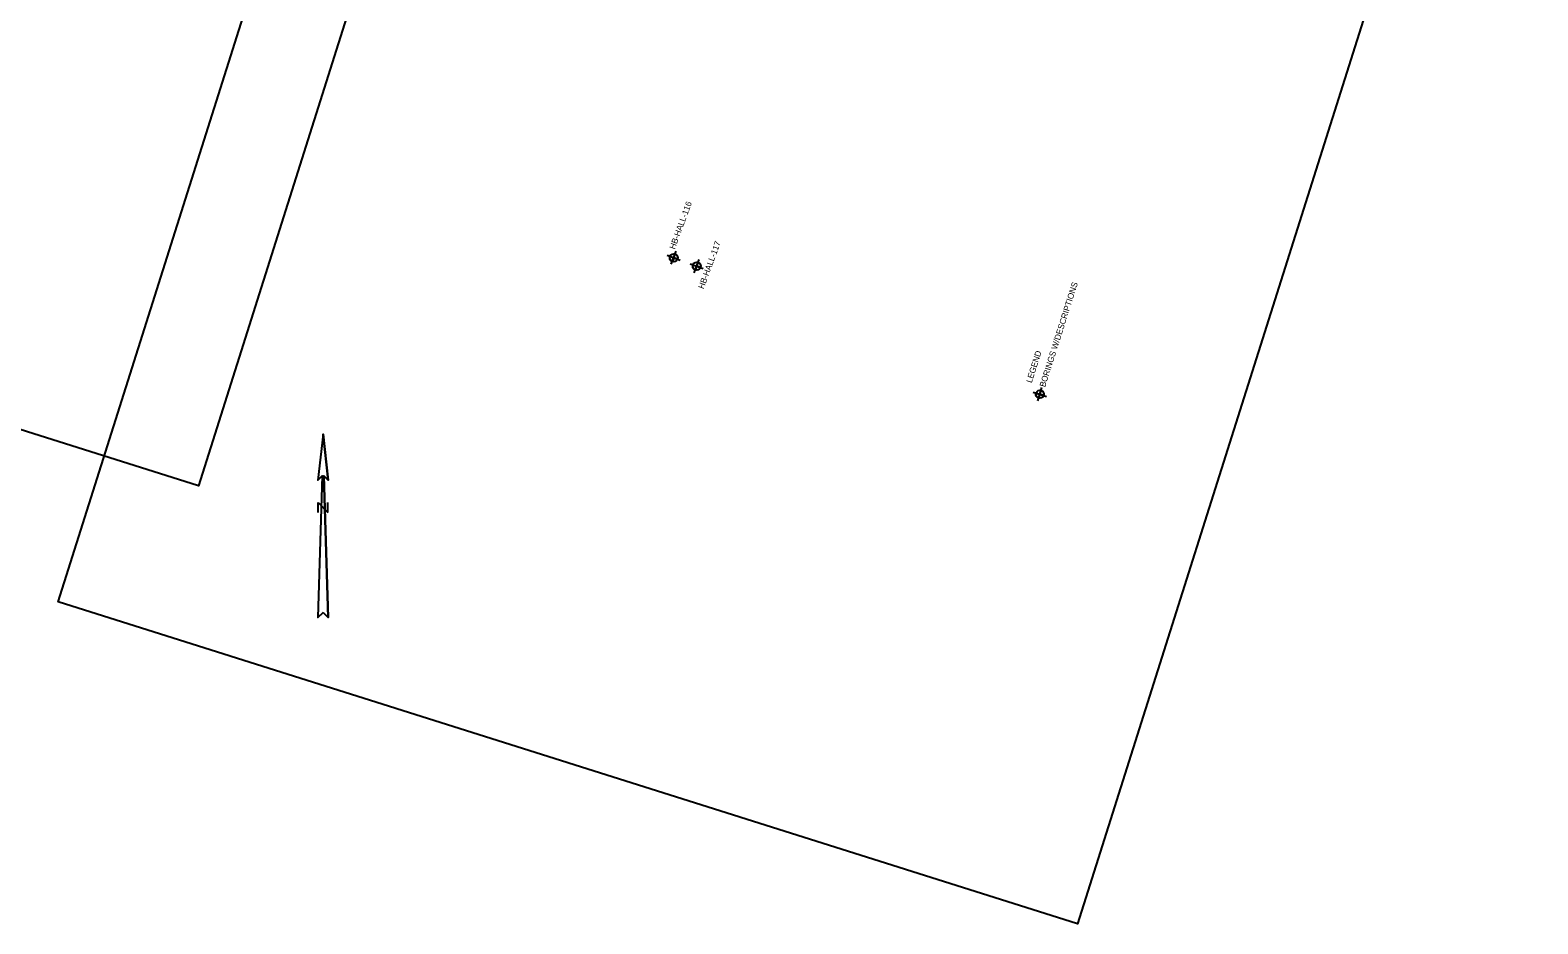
# Model space of a CAD drawing. Extents: x 1136334 to 1137758, y 528745 to 531454.
# Drawn here: x 1136833 to 1137574, y 528745 to 529184 of the extents above; entities that cross this region are included whole.
import ezdxf

# ---------------------------------------------------------------- set-up
doc = ezdxf.new("R2010")
doc.units = 0
for name, color, linetype in [('H_V CONTROLS', 7, 'Continuous'), ('PLOT BOUNDARY', 7, 'Continuous'), ('ROCKS', 7, 'Continuous')]:
    doc.layers.add(name, color=color, linetype=linetype)

msp = doc.modelspace()

# ---------------------------------------------------------------- linework, layer by layer
at = {"layer": 'H_V CONTROLS'}
for p, q in [((1137325.97, 529006.4), (1137332.54, 529004.33)), ((1137328.22, 529002.08), (1137330.29, 529008.65)), ((1136977.28, 528985.74), (1136974.78, 528963.24)), ((1136977.28, 528985.74), (1136979.78, 528963.24)), ((1136976.9, 528965.36), (1136974.78, 528963.24)), ((1136976.9, 528965.36), (1136974.78, 528895.74)), ((1136977.67, 528965.36), (1136979.78, 528963.24)), ((1136977.67, 528965.36), (1136979.78, 528895.74)), ((1136977.28, 528898.24), (1136974.78, 528895.74)), ((1136977.28, 528898.24), (1136979.78, 528895.74))]:
    msp.add_line(p, q, dxfattribs=at)
for points in [[(1137329.26, 529005.37), (1137328.66, 529003.49), (1137328.41, 529003.59), (1137328.17, 529003.73), (1137327.95, 529003.9), (1137327.73, 529004.12), (1137327.59, 529004.32), (1137327.42, 529004.65), (1137327.35, 529004.87), (1137327.29, 529005.32), (1137327.31, 529005.67), (1137327.38, 529005.96)], [(1137329.26, 529005.37), (1137329.85, 529007.24), (1137330.1, 529007.14), (1137330.34, 529007.01), (1137330.56, 529006.84), (1137330.78, 529006.61), (1137330.93, 529006.41), (1137331.09, 529006.09), (1137331.16, 529005.87), (1137331.22, 529005.41), (1137331.2, 529005.06), (1137331.13, 529004.78)]]:
    msp.add_lwpolyline(points, close=True, dxfattribs=at)
for points in [[(1136977.28, 528898.24), (1136979.78, 528895.74), (1136977.67, 528965.36), (1136979.78, 528963.24), (1136977.28, 528985.74), (1136974.78, 528963.24), (1136976.9, 528965.36), (1136974.78, 528895.74), (1136977.28, 528898.24)], [(1136974.92, 528947.24), (1136974.92, 528952.24)], [(1136974.92, 528952.24), (1136979.65, 528947.24)], [(1136979.65, 528947.24), (1136979.65, 528952.24)]]:
    msp.add_lwpolyline(points, dxfattribs=at)
msp.add_circle((1137329.26, 529005.37), 1.97, dxfattribs=at)
at = {"layer": 'PLOT BOUNDARY'}
for points in [[(1137142.07, 529675.56), (1136916.06, 528960.42), (1136415.46, 529118.63), (1136641.47, 529833.77)], [(1137573.8, 529460.37), (1137347.79, 528745.23), (1136847.2, 528903.44), (1137073.21, 529618.57)]]:
    msp.add_lwpolyline(points, close=True, dxfattribs=at)
at = {"layer": 'ROCKS'}
for p, q in [((1137146.25, 529073.62), (1137152.72, 529071.26)), ((1137148.3, 529069.21), (1137150.67, 529075.67)), ((1137159.57, 529065.09), (1137161.94, 529071.55)), ((1137157.52, 529069.5), (1137163.99, 529067.14))]:
    msp.add_line(p, q, dxfattribs=at)
for points in [[(1137149.49, 529072.44), (1137148.81, 529070.59), (1137148.56, 529070.71), (1137148.33, 529070.85), (1137148.12, 529071.03), (1137147.91, 529071.27), (1137147.77, 529071.48), (1137147.62, 529071.81), (1137147.56, 529072.03), (1137147.52, 529072.48), (1137147.56, 529072.83), (1137147.64, 529073.12)], [(1137149.49, 529072.44), (1137150.16, 529074.29), (1137150.41, 529074.18), (1137150.65, 529074.03), (1137150.86, 529073.85), (1137151.07, 529073.62), (1137151.2, 529073.41), (1137151.35, 529073.08), (1137151.41, 529072.85), (1137151.46, 529072.4), (1137151.41, 529072.05), (1137151.34, 529071.77)], [(1137160.76, 529068.32), (1137161.43, 529070.17), (1137161.68, 529070.05), (1137161.92, 529069.91), (1137162.13, 529069.73), (1137162.34, 529069.5), (1137162.47, 529069.29), (1137162.62, 529068.95), (1137162.68, 529068.73), (1137162.73, 529068.28), (1137162.68, 529067.93), (1137162.6, 529067.64)], [(1137160.76, 529068.32), (1137160.08, 529066.47), (1137159.83, 529066.59), (1137159.6, 529066.73), (1137159.39, 529066.91), (1137159.18, 529067.14), (1137159.04, 529067.35), (1137158.89, 529067.68), (1137158.83, 529067.91), (1137158.79, 529068.36), (1137158.83, 529068.71), (1137158.91, 529069)]]:
    msp.add_lwpolyline(points, close=True, dxfattribs=at)
for centre in [(1137149.49, 529072.44), (1137160.76, 529068.32)]:
    msp.add_circle(centre, 1.97, dxfattribs=at)

# ---------------------------------------------------------------- texts
at = {"layer": 'H_V CONTROLS'}
for s, height, p in [('BORINGS W/DESCRIPTIONS', 2.9528, (1137331.83, 529008.66)), ('LEGEND', 2.953, (1137325.26, 529010.73))]:
    msp.add_text(s, height=height, rotation=72.50788, dxfattribs=at).set_placement(p)
at = {"layer": 'ROCKS'}
for s, p in [('HB-HALL-116', (1137150.01, 529076.31)), ('HB-HALL-117', (1137164.17, 529056.85))]:
    msp.add_text(s, height=2.9528, rotation=69.90541, dxfattribs=at).set_placement(p)

doc.saveas('drawing.dxf')
